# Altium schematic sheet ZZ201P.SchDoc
size A3
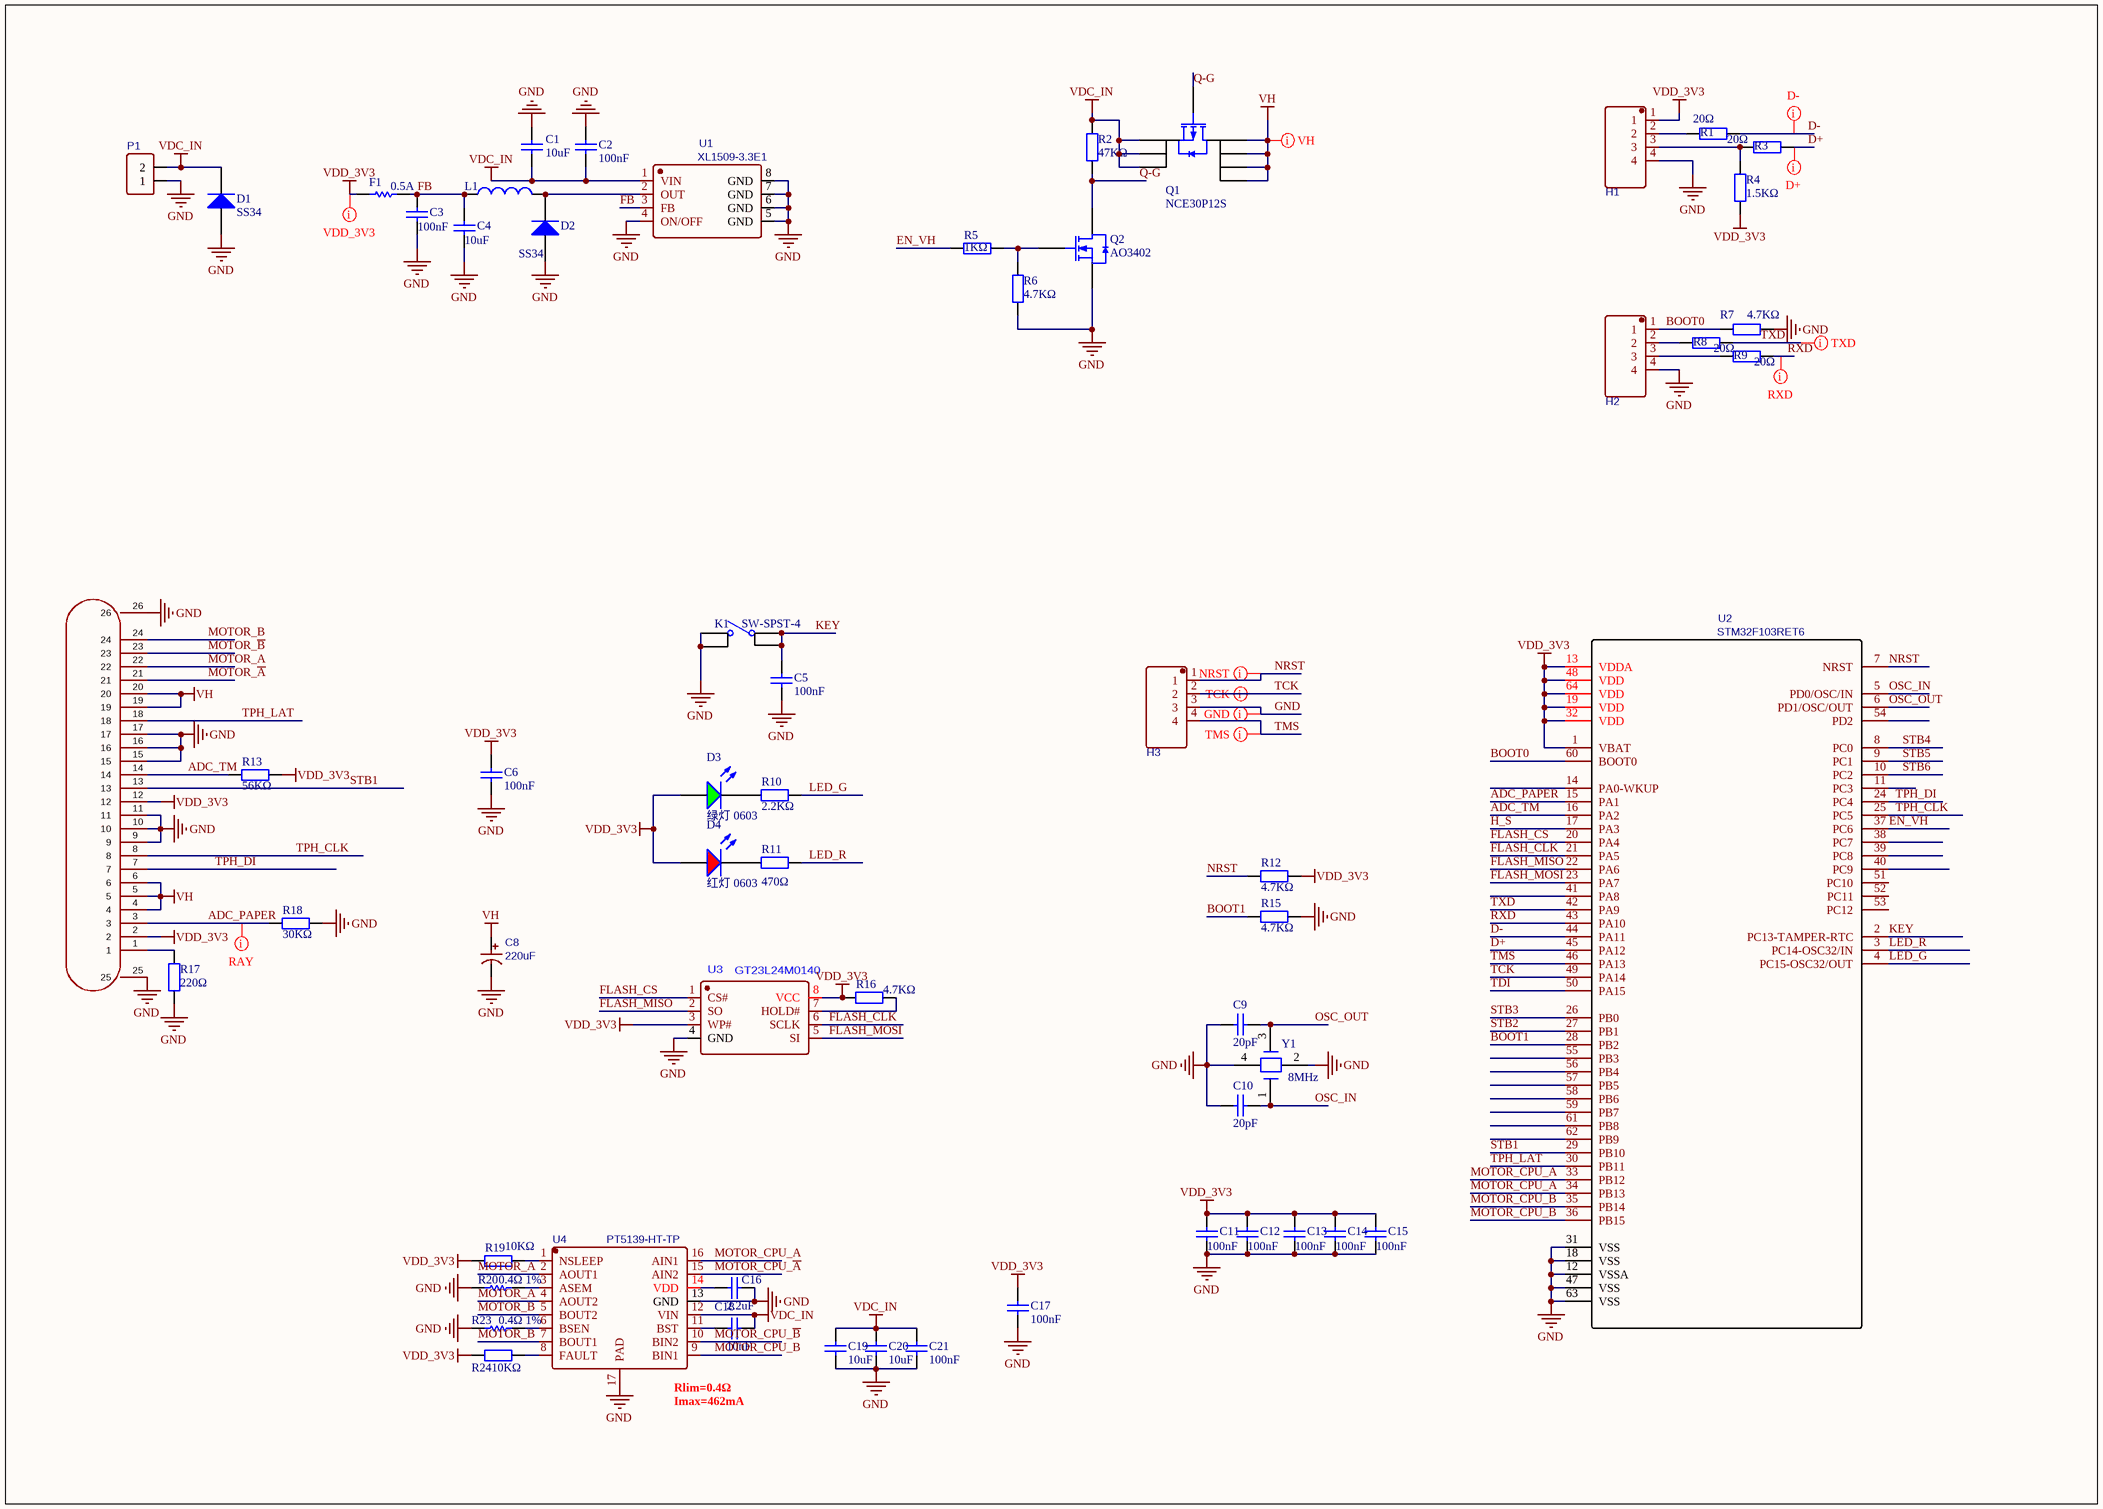
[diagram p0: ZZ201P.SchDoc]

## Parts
C1  10uF  [0603_C]
C2  100nF  [0603_C]
C3  100nF  [0603_C]
C4  10uF  [0603_C]
C5  100nF  [0603_C]
C6  100nF  [0603_C]
C8  220uF  [CASE-B_3528]
C9  20pF  [0603_C]
C10  20pF  [0603_C]
C11  100nF  [0603_C]
C12  100nF  [0603_C]
C13  100nF  [0603_C]
C14  100nF  [0603_C]
C15  100nF  [0603_C]
C16  2.2uF  [0603_C]
C17  100nF  [0603_C]
C18  10nF  [0603_C]
C19  10uF  [0603_C]
C20  10uF  [0603_C]
C21  100nF  [0603_C]
D1  SS34  [SMA_L4.4-W2.8-LS5.4-RD]
D2  SS34  [SMA_L4.4-W2.8-LS5.4-RD]
D3  绿灯 0603  [0603_LED_S1]
D4  红灯 0603  [0603_LED_S1]
F1  0.5A  [0603_R]
FPC?  afc07-s24eca-00  [2P-P2.54-V]  (value not drawn)
H1  77311-462K05LF  [PCBComponent_1 - duplicate]  (value not drawn)
H2  77311-462K05LF  [PCBComponent_1 - duplicate]  (value not drawn)
H3  77311-462K05LF  [5P_1.25]  (value not drawn)
K1  SW-SPST-4  [KEY-SMD_4P-L5.2-W5.2-P3.70-LS6.4]
L1  4040-47uH  [IND-SMD_L4.0-W4.0_FNR40XXS]  (value not drawn)
P1  Header-Female-2.54_1x2  [2P-P2.54-V]  (value not drawn)
Q1  NCE30P12S  [SOIC-8_150mil]
Q2  AO3402  [SOT-23]
R1  20Ω  [0603_R]
R2  47KΩ  [0603_R]
R3  20Ω  [0603_R]
R4  1.5KΩ  [0603_R]
R5  1KΩ  [0603_R]
R6  4.7KΩ  [0603_R]
R7  4.7KΩ  [0603_R]
R8  20Ω  [0603_R]
R9  20Ω  [0603_R]
R10  2.2KΩ  [0603_R]
R11  470Ω  [0603_R]
R12  4.7KΩ  [0603_R]
R13  56KΩ  [0603_R]
R15  4.7KΩ  [0603_R]
R16  4.7KΩ  [0603_R]
R17  220Ω  [0603_C]
R18  30KΩ  [0603_R]
R19  10KΩ  [0603_R]
R20  0.4Ω 1%  [1206_r]
R23  0.4Ω 1%  [1206_R]
R24  10KΩ  [0603_R]
U1  XL1509-3.3E1  [SOP-8_L4.9-W3.9-P1.27-LS6.0-BL]
U2  STM32F103RET6  [LQFP-64_L10.0-W10.0-P0.50-LS12.0-BL]
U3  GT23L24M0140  [SOP-8_L5.3-W5.3-P1.27-LS8.0-BL]
U4  PT5139-HT-TP  [HTSSOP-16_L5.0-W4.4-P0.65-LS6.4-BL-EP]
Y1  8MHz  [XT_3225_4]

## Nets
GND: C1.2 C2.2 C3.2 C4.2 C5.2 C6.1 C8.2 C9.1 C10.1 C11.1 C12.1 C13.1 C14.1 C15.1 C16.2 C17.1 C19.1 C20.1 C21.1 D1.1(A) D2.1(A) FPC?.9 FPC?.10 FPC?.11 FPC?.15 FPC?.16 FPC?.17 FPC?.25 FPC?.26 H1.4 H2.4 H3.3 K1.3 K1.4(NO) P1.1 Q2.2(S) R6.1 R7.2 R15.1 R17.1 R18.2 R20.2 R23.2 U1.4(ON/OFF) U1.5(GND) U1.6(GND) U1.7(GND) U1.8(GND) U2.12(VSSA) U2.18(VSS) U2.31(VSS) U2.47(VSS) U2.63(VSS) U3.4(GND) U4.13(GND) U4.17(PAD) Y1.2 Y1.4
VDC_IN: C1.1 C2.1 C18.2 C19.2 C20.2 C21.2 D1.2(K) P1.2 Q1.1(S) Q1.2(S) Q1.3(S) R2.2 U1.1(VIN) U4.12(VIN)
VDD_3V3: C6.2 C11.2 C12.2 C13.2 C14.2 C15.2 C17.2 D3.A D4.A F1.1 FPC?.2 FPC?.12 H1.1 R4.1 R12.1 R13.2 R16.2 R19.2 R24.2 U2.1(VBAT) U2.13(VDDA) U2.19(VDD) U2.32(VDD) U2.48(VDD) U2.64(VDD) U3.3(WP#) U3.8(VCC)
VH: C8.1 FPC?.4 FPC?.5 FPC?.6 FPC?.19 FPC?.20 Q1.5(D) Q1.6(D) Q1.7(D) Q1.8(D)
ADC_PAPER: FPC?.3 R18.1 U2.15(PA1)
ADC_TM: FPC?.14 R13.1 U2.16(PA2)
BOOT0: H2.1 R7.1 U2.60(BOOT0)
BOOT1: R15.2 U2.28(PB2)
D+: R3.2 U2.45(PA12)
D-: R1.2 U2.44(PA11)
EN_VH: R5.2 U2.37(PC6)
FB: C3.1 C4.1 F1.2 L1.1 U1.3(FB)
FLASH_CLK: U2.21(PA5) U3.6(SCLK)
FLASH_CS: U2.20(PA4) U3.1(CS#)
FLASH_MISO: U2.22(PA6) U3.2(SO)
FLASH_MOSI: U2.23(PA7) U3.5(SI)
H_S: U2.17(PA3)
KEY: C5.1 K1.1(COMMON) K1.2 U2.2(PC13-TAMPER-RTC)
LED_G: R10.2 U2.4(PC15-OSC32/OUT)
LED_R: R11.2 U2.3(PC14-OSC32/IN)
MOTOR_A: FPC?.22 U4.2(AOUT1)
MOTOR_~{A}: FPC?.21 U4.4(AOUT2)
MOTOR_B: FPC?.24 U4.7(BOUT1)
MOTOR_~{B}: FPC?.23 U4.5(BOUT2)
MOTOR_CPU_A: U2.33(PB12) U4.16(AIN1)
MOTOR_CPU_~{A}: U2.34(PB13) U4.15(AIN2)
MOTOR_CPU_B: U2.36(PB15) U4.9(BIN1)
MOTOR_CPU_~{B}: U2.35(PB14) U4.10(BIN2)
NRST: H3.1 R12.2 U2.7(NRST)
OSC_IN: C10.2 U2.5(PD0/OSC/IN) Y1.1(OSC1)
OSC_OUT: C9.2 U2.6(PD1/OSC/OUT) Y1.3(OSC2)
Q-G: Q1.4(G) Q2.3(D) R2.1
RXD: R9.2 U2.43(PA10)
STB1: FPC?.13 U2.29(PB10)
STB2: U2.27(PB1)
STB3: U2.26(PB0)
STB4: U2.8(PC0)
STB5: U2.9(PC1)
STB6: U2.10(PC2)
TCK: H3.2 U2.49(PA14)
TDI: U2.50(PA15)
TMS: H3.4 U2.46(PA13)
TPH_CLK: FPC?.8 U2.25(PC5)
TPH_DI: FPC?.7 U2.24(PC4)
TPH_LAT: FPC?.18 U2.30(PB11)
TXD: R8.2 U2.42(PA9)
NetC16_1: C16.1 U4.14(VDD)
NetC18_1: C18.1 U4.11(BST)
NetD2_2: D2.2(K) L1.2 U1.2(OUT)
NetD3_K: D3.K R10.1
NetD4_K: D4.K R11.1
NetFPC?_1: FPC?.1 R17.2
NetH1_2: H1.2 R1.1
NetH1_3: H1.3 R3.1 R4.2
NetH2_2: H2.2 R8.1
NetH2_3: H2.3 R9.1
NetQ2_1: Q2.1(G) R5.1 R6.2
NetR16_1: R16.1 U3.7(HOLD#)
NetR19_1: R19.1 U4.1(NSLEEP)
NetR20_1: R20.1 U4.3(ASEM)
NetR23_1: R23.1 U4.6(BSEN)
NetR24_1: R24.1 U4.8(FAULT)

Not connected (* = marked no-connect by the designer): U2 11(PC3) 14(PA0-WKUP) 38(PC7) 39(PC8) 40(PC9) 41(PA8) 51(PC10) 52(PC11) 53(PC12) 54(PD2) 55(PB3) 56(PB4) 57(PB5) 58(PB6) 59(PB7) 61(PB8) 62(PB9)

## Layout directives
Column: TestVectorIndex: ADC_PAPER, D+, D-, GND, NRST, RXD, TCK, TMS, TXD, VDD_3V3, VH

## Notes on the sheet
- (near U4) Rlim=0.4Ω
- (near U4) Imax=462mA

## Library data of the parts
C1 C19 C20 = 0805 10uF (106) 10% 25V: 贴片电容
C2-C6 C11-C15 C17 C21 = 0603 100nF (104) 10% 50V: 贴片电容
C8 = 10uF: BOM_Manufacturer: ValuePro; BOM_Manufacturer Part: 10uF 25V RHOS; nameAlias: Capacitance
C9 C10 = 0603 10pF (100) 5% 50V: 贴片电容
C16 = 0805 2.2uF (225) 20% 50V: 贴片电容
C18 = 0603 10nF (103) 10% 50V: 贴片电容
D1 = SMA(DO-214AC) M7: 二极管; 备注: 1N4007 4007 编号C2464 已经停售, 使用新物料编号C95872
D2 = SOD-323 1N4148WS T4: 二极管
D3 = 0603 绿灯: 发光二极管
D4 = 0603 红灯: 发光二极管
F1 = Res1: Resistor
FPC? = afc07-s24eca-00: 锁定特性:抽屉式;触点类型:上接;触点数量:24P;间距:0.5mm;安装类型:卧贴;; Manufacturer: JS(钜硕电子); AddInBom: yes; ModelId: 6bbc45c14a884fb5877d6cdbe51e6fe5; ModelName: FPC-SMD_AFC07-S24ECA-00; ModelTransform: 692.912,204.724,0,0,0,0,0.002,-58.424,0; Locking Feature: 抽屉式; Number of Contacts: 24P; Pitch: 0.5mm; FFC, FCB Thickness: 0.3mm
H1-H3 = 77311-462K05LF: BOM_Manufacturer: Amphenol ICC; Contributor: LCSC
L1 = Inductor: Code_IEC: 1005; Value: 48uH
P1 = Header-Female-2.54_1x2: BOM_Manufacturer: BOOMELE; BOM_Manufacturer Part: 2.54-1*2PFemale
Q1 = AO4407A: MOS(场效应管)
Q2 = AO3400A N道沟 X0YV1T SOT-23: MOS(场效应管)
R1 R3 R4 R8 R9 = 0603 100Ω (1000) 1%: 贴片电阻
R2 = 0603 47KΩ (4702) 1%: 贴片电阻
R5 = 0603 470Ω (4700) 1%: 贴片电阻
R6 R7 R12 R15 R16 = 0603 4.7KΩ (4701) 1%: 贴片电阻
R10 R11 = 0603 2KΩ (2001) 1%: 贴片电阻
R13 R19 R24 = 0603 10KΩ (1002) 1%: 贴片电阻
R17 = 0603 200Ω (2000) 1%: 贴片电阻
R18 = 0603 30KΩ (3002) 1%: 贴片电阻
R20 R23 = Res: Resistor; Value: 1K
U1 = XL1509-3.3E1: BOM_Manufacturer: XLSEMI; SMT Type: Extend
U2 = STM32F103RET6: BOM_Manufacturer: STMicroelectronics; SMT Type: Basic
U3 = GD25Q64CSIG
U4 = PT5139-HT-TP: BOM_Manufacturer: Princeton Tech; Contributor: LCSC
Y1 = XTAL_4: Crystal Oscillator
